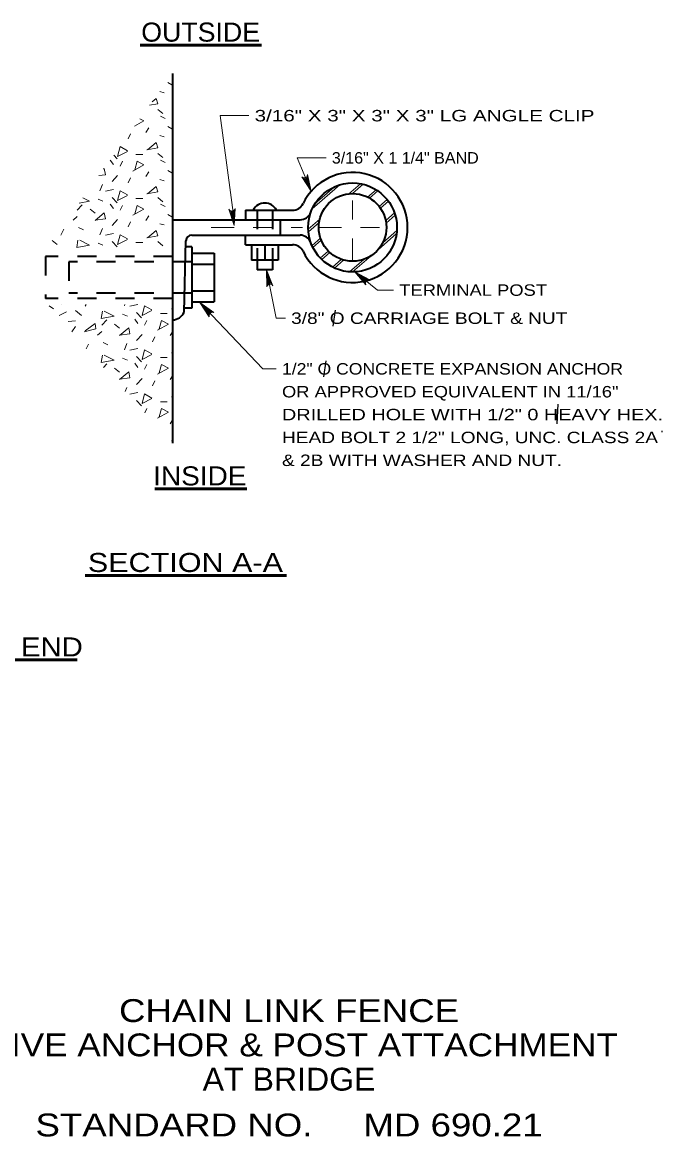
# Model space of a CAD drawing. Extents: x -29.89 to -22.78, y 99.65 to 109.34.
# Drawn here: x -26.25 to -22.88, y 99.65 to 105.5 of the extents above; entities that cross this region are included whole.
import ezdxf
from ezdxf.enums import TextEntityAlignment as Align

# ---------------------------------------------------------------- set-up
doc = ezdxf.new("R2010")
doc.units = 0
doc.header["$LTSCALE"] = 0.024
doc.linetypes.add('DOT_DASHED', pattern=[7.7, 5, -1.2, 0.3, -1.2])
doc.linetypes.add('SHORT_DASHED', pattern=[2.7, 1.5, -1.2])
for name, color, linetype, lineweight in [('1', 7, 'Continuous', 35), ('10', 7, 'Continuous', 13), ('12', 7, 'Continuous', 53), ('13', 7, 'Continuous', 25), ('6', 7, 'Continuous', 13)]:
    doc.layers.add(name, color=color, linetype=linetype, lineweight=lineweight)

msp = doc.modelspace()

# ---------------------------------------------------------------- linework, layer by layer
at = {"layer": '1'}
for p, q in [((-25.45667, 105.22985), (-25.45667, 103.29046)), ((-25.45667, 104.46217), (-24.78685, 104.46217)), ((-25.07283, 104.51269), (-24.82575, 104.51269)), ((-25.07283, 104.51269), (-25.07283, 104.46217)), ((-24.891, 104.46217), (-24.891, 104.38137)), ((-25.39606, 103.97733), (-25.38594, 104.35187)), ((-25.35565, 104.38137), (-24.78685, 104.38137)), ((-25.07283, 104.33085), (-25.07283, 104.38137)), ((-25.35565, 104.32075), (-25.38596, 104.32075)), ((-25.35565, 104.32075), (-25.35565, 103.99752)), ((-25.35469, 104.28652), (-25.23825, 104.28652)), ((-25.23825, 104.28652), (-25.23825, 104.03179)), ((-25.07283, 104.33085), (-24.82575, 104.33085)), ((-25.04252, 104.33085), (-25.04252, 104.25006)), ((-24.97181, 104.33085), (-24.97181, 104.25006)), ((-24.9011, 104.33085), (-24.9011, 104.25006)), ((-25.35469, 104.22829), (-25.23825, 104.22829)), ((-24.9011, 104.25006), (-25.04252, 104.25006)), ((-25.01223, 104.25006), (-25.01223, 104.19954)), ((-24.93142, 104.25006), (-24.93142, 104.19954)), ((-24.93142, 104.19954), (-25.01223, 104.19954)), ((-25.35469, 104.09), (-25.23825, 104.09)), ((-25.35565, 103.99752), (-25.39552, 103.99752)), ((-25.35469, 104.03179), (-25.23825, 104.03179))]:
    msp.add_line(p, q, dxfattribs=at)
at = {"layer": '1', "linetype": 'SHORT_DASHED'}
for p, q in [((-25.45667, 104.46217), (-25.35565, 104.46217)), ((-25.01223, 104.51269), (-25.01223, 104.25006)), ((-24.93142, 104.51269), (-24.93142, 104.25006)), ((-26.12333, 104.26925), (-26.12333, 104.04904)), ((-25.45667, 104.26925), (-26.12333, 104.26925)), ((-26.00212, 104.24096), (-26.00212, 104.07733)), ((-25.35565, 104.24096), (-26.00212, 104.24096)), ((-25.45667, 104.04904), (-26.12333, 104.04904)), ((-25.35565, 104.07733), (-26.00212, 104.07733))]:
    msp.add_line(p, q, dxfattribs=at)
at = {"layer": '1'}
for radius in [0.23333, 0.17778]:
    msp.add_circle((-24.51081, 104.42177), radius, dxfattribs=at)
for centre, radius, start, end in [((-24.51081, 104.42177), 0.28889, 205.69151, 154.30843), ((-24.97182, 104.48152), 0.06815, 27.21203, 152.78797), ((-24.82575, 104.57329), 0.06061, 270, 334.30843), ((-24.78684, 104.52278), 0.06061, 270, 339.901), ((-25.35564, 104.35106), 0.0303, 90, 178.45183), ((-24.78684, 104.32076), 0.06061, 20.09892, 90), ((-24.82575, 104.27025), 0.06061, 25.69151, 90), ((-25.45735, 104.0036), 0.06669, 270.58756, 336.79258)]:
    msp.add_arc(centre, radius, start, end, dxfattribs=at)
at = {"layer": '10', "linetype": 'DOT_DASHED'}
for p, q in [((-24.51081, 104.244), (-24.51081, 104.5945)), ((-25.2535, 104.42177), (-24.77335, 104.42177)), ((-24.68858, 104.42177), (-24.33302, 104.42177))]:
    msp.add_line(p, q, dxfattribs=at)
at = {"layer": '10'}
for p, q in [((-24.37971, 104.09292), (-24.4994, 104.18871)), ((-24.29552, 104.09292), (-24.37971, 104.09292))]:
    msp.add_line(p, q, dxfattribs=at)
at = {"layer": '10', "lineweight": 25}
for p, q in [((-24.61329, 103.90283), (-24.60112, 103.9881)), ((-24.66181, 103.63706), (-24.64965, 103.72235))]:
    msp.add_line(p, q, dxfattribs=at)
at = {"layer": '10'}
for points in [[(-25.05569, 105.0085), (-25.20694, 105.0085), (-25.13229, 104.46217)], [(-24.72802, 104.61225), (-24.80115, 104.78704), (-24.6499, 104.78704)], [(-24.72802, 104.61225), (-24.77733, 104.68727), (-24.77037, 104.68281), (-24.76356, 104.68187), (-24.75771, 104.68323), (-24.75265, 104.68644), (-24.74854, 104.69196), (-24.74681, 104.70006), (-24.72802, 104.61225), (-24.74854, 104.69196), (-24.75265, 104.68644), (-24.72802, 104.61225), (-24.75771, 104.68323), (-24.76356, 104.68187), (-24.72802, 104.61225), (-24.77037, 104.68281)], [(-25.13229, 104.43187), (-25.16065, 104.51708), (-25.15504, 104.51098), (-25.14871, 104.50831), (-25.14271, 104.5081), (-25.13698, 104.50992), (-25.13158, 104.51419), (-25.12783, 104.52156), (-25.13229, 104.43187), (-25.13158, 104.51419), (-25.13698, 104.50992), (-25.13229, 104.43187), (-25.14271, 104.5081), (-25.14871, 104.50831), (-25.13229, 104.43187), (-25.15504, 104.51098)], [(-24.86385, 103.94548), (-24.91181, 103.94548), (-24.96227, 104.19954)], [(-24.96227, 104.19954), (-24.92883, 104.11619), (-24.93479, 104.12196), (-24.94127, 104.12423), (-24.94727, 104.12408), (-24.95287, 104.12194), (-24.958, 104.11733), (-24.96131, 104.10975), (-24.96227, 104.19954), (-24.958, 104.11733), (-24.95287, 104.12194), (-24.96227, 104.19954), (-24.94727, 104.12408), (-24.94127, 104.12423), (-24.96227, 104.19954), (-24.93479, 104.12196)], [(-24.4994, 104.18871), (-24.42015, 104.14648), (-24.4284, 104.14704), (-24.43483, 104.14462), (-24.43933, 104.14062), (-24.44223, 104.13537), (-24.44319, 104.12856), (-24.44083, 104.12065), (-24.4994, 104.18871), (-24.44319, 104.12856), (-24.44223, 104.13537), (-24.4994, 104.18871), (-24.43933, 104.14062), (-24.43483, 104.14462), (-24.4994, 104.18871), (-24.4284, 104.14704)], [(-24.91181, 103.67971), (-24.9819, 103.67971), (-25.3166, 104.03179)], [(-25.31242, 104.02798), (-25.2396, 103.97542), (-25.24771, 103.97708), (-25.25442, 103.97556), (-25.2594, 103.97221), (-25.263, 103.9674), (-25.26487, 103.96077), (-25.2636, 103.9526), (-25.31242, 104.02798), (-25.26487, 103.96077), (-25.263, 103.9674), (-25.31242, 104.02798), (-25.2594, 103.97221), (-25.25442, 103.97556), (-25.31242, 104.02798), (-25.24771, 103.97708)]]:
    msp.add_lwpolyline(points, dxfattribs=at)
at = {"layer": '12'}
for p, q in [((-25.62696, 105.37844), (-24.98935, 105.37844)), ((-25.55012, 103.04929), (-25.06546, 103.04929)), ((-25.91608, 102.59488), (-24.85775, 102.59488)), ((-29.60256, 102.15167), (-25.95775, 102.15167))]:
    msp.add_line(p, q, dxfattribs=at)
at = {"layer": '13'}
msp.add_line((-23.4324, 103.49381), (-23.43829, 103.39044), dxfattribs=at)
at = {"layer": '6'}
for p, q in [((-25.48185, 105.18283), (-25.4594, 105.16998)), ((-25.52358, 105.13469), (-25.5011, 105.12827)), ((-25.53321, 105.04162), (-25.50752, 105.01917)), ((-25.52037, 105.00631), (-25.49469, 104.99348)), ((-25.5974, 104.91967), (-25.58133, 104.94535)), ((-25.48185, 104.95177), (-25.4594, 104.93894)), ((-25.67762, 104.91325), (-25.69046, 104.88758)), ((-25.52358, 104.90362), (-25.5011, 104.89721)), ((-25.53321, 104.81056), (-25.50752, 104.7881)), ((-25.78352, 104.77525), (-25.76748, 104.75279)), ((-25.76571, 104.80135), (-25.74821, 104.78169)), ((-25.71933, 104.76883), (-25.73217, 104.74317)), ((-25.64873, 104.80415), (-25.61344, 104.80415)), ((-25.52037, 104.77525), (-25.49469, 104.76242)), ((-25.745, 104.69502), (-25.7739, 104.66294)), ((-25.5974, 104.6886), (-25.58133, 104.71429)), ((-25.48185, 104.72071), (-25.4594, 104.70788)), ((-25.82523, 104.6469), (-25.83808, 104.61479)), ((-25.67762, 104.68219), (-25.69046, 104.65652)), ((-25.52358, 104.67256), (-25.5011, 104.66615)), ((-24.57829, 104.64512), (-24.72285, 104.51917)), ((-24.46958, 104.65144), (-24.53035, 104.59848)), ((-24.45596, 104.64856), (-24.51142, 104.60025)), ((-25.76748, 104.62123), (-25.80919, 104.61158)), ((-25.7739, 104.5795), (-25.74821, 104.55062)), ((-25.53321, 104.5795), (-25.50752, 104.55704)), ((-24.60819, 104.63381), (-24.70754, 104.54723)), ((-24.38746, 104.61983), (-24.43158, 104.5814)), ((-24.37781, 104.6135), (-24.42146, 104.57546)), ((-25.95681, 104.5121), (-25.93115, 104.541)), ((-25.88942, 104.51852), (-25.86375, 104.49606)), ((-25.84771, 104.56987), (-25.82202, 104.56025)), ((-25.78352, 104.54421), (-25.76748, 104.52173)), ((-25.71933, 104.53777), (-25.73217, 104.5121)), ((-25.64873, 104.57308), (-25.61344, 104.57308)), ((-25.52037, 104.54421), (-25.49469, 104.53135)), ((-24.32881, 104.56779), (-24.37073, 104.53125)), ((-24.32204, 104.55894), (-24.36415, 104.52225)), ((-25.97927, 104.46075), (-25.95681, 104.48002)), ((-25.745, 104.46398), (-25.7739, 104.43187)), ((-25.5974, 104.45754), (-25.58133, 104.48323)), ((-25.48185, 104.48965), (-25.4594, 104.47681)), ((-24.68317, 104.46529), (-24.74396, 104.41233)), ((-24.29033, 104.49815), (-24.33671, 104.45773)), ((-24.28667, 104.4866), (-24.33454, 104.44487)), ((-26.04346, 104.38054), (-26.02742, 104.41262)), ((-25.9504, 104.42225), (-25.92473, 104.40942)), ((-25.82523, 104.41583), (-25.83808, 104.38375)), ((-25.67762, 104.45112), (-25.69046, 104.42546)), ((-25.52358, 104.4415), (-25.5011, 104.43508)), ((-24.68671, 104.44748), (-24.74298, 104.39846)), ((-24.27802, 104.40571), (-24.35256, 104.34073)), ((-26.08885, 104.35329), (-26.06271, 104.3324)), ((-25.76748, 104.39017), (-25.80919, 104.38054)), ((-25.7739, 104.34844), (-25.74821, 104.31956)), ((-25.64873, 104.34202), (-25.61344, 104.34202)), ((-25.53321, 104.34844), (-25.50752, 104.32598)), ((-24.67902, 104.36575), (-24.72387, 104.32667)), ((-24.67527, 104.35427), (-24.71892, 104.31625)), ((-24.27971, 104.38948), (-24.37704, 104.30467)), ((-25.84771, 104.33881), (-25.82202, 104.32919)), ((-24.6384, 104.29798), (-24.68033, 104.26144)), ((-24.6304, 104.29023), (-24.6725, 104.25354)), ((-24.57023, 104.25423), (-24.6166, 104.21381)), ((-24.55779, 104.25031), (-24.60567, 104.2086)), ((-24.45217, 104.25394), (-24.52671, 104.18898)), ((-24.4131, 104.27325), (-24.51042, 104.18844)), ((-26.10421, 104.01127), (-26.08175, 103.99523)), ((-26.03998, 104.01773), (-26.04002, 104.01769)), ((-25.91487, 104.00806), (-25.91004, 104.01773)), ((-25.7069, 104.01773), (-25.70948, 104.01127)), ((-25.63887, 104.01769), (-25.6806, 104.00806)), ((-25.46237, 103.99523), (-25.45667, 103.99617)), ((-25.45667, 103.99735), (-25.45917, 103.99523)), ((-26.01435, 103.97917), (-26.05285, 103.95992)), ((-25.96621, 103.98558), (-25.93412, 103.95992)), ((-25.82823, 103.90856), (-25.80254, 103.93746)), ((-25.7191, 103.96633), (-25.69344, 103.95671)), ((-25.65492, 103.94067), (-25.63887, 103.91821)), ((-25.64529, 103.97596), (-25.61962, 103.94708)), ((-25.59075, 103.93425), (-25.60358, 103.90856)), ((-25.52015, 103.96954), (-25.48483, 103.96954)), ((-26.00473, 103.92783), (-25.96621, 103.93104)), ((-25.98548, 103.87327), (-25.96621, 103.90215)), ((-25.85069, 103.85723), (-25.82823, 103.87648)), ((-25.76083, 103.915), (-25.73515, 103.89252)), ((-25.82181, 103.81871), (-25.79612, 103.80588)), ((-25.61642, 103.86044), (-25.64529, 103.82833)), ((-25.54902, 103.8476), (-25.56185, 103.82192)), ((-25.46879, 103.85402), (-25.45667, 103.87342)), ((-25.91056, 103.7856), (-25.89881, 103.80908)), ((-25.69665, 103.81229), (-25.70948, 103.78021)), ((-25.63887, 103.78663), (-25.6806, 103.777)), ((-25.46237, 103.76417), (-25.45667, 103.7651)), ((-25.45667, 103.76631), (-25.45917, 103.76417)), ((-25.81998, 103.68679), (-25.80254, 103.7064)), ((-25.7191, 103.73527), (-25.69344, 103.72565)), ((-25.65492, 103.7096), (-25.63887, 103.68715)), ((-25.64529, 103.7449), (-25.61962, 103.71602)), ((-25.59075, 103.70319), (-25.60358, 103.67752)), ((-25.52015, 103.73848), (-25.48483, 103.73848)), ((-25.76083, 103.68394), (-25.73515, 103.66146)), ((-25.46879, 103.62296), (-25.45667, 103.64235)), ((-25.69665, 103.58123), (-25.70471, 103.56106)), ((-25.61642, 103.62937), (-25.64529, 103.59729)), ((-25.54902, 103.61654), (-25.56185, 103.59085)), ((-25.63887, 103.55556), (-25.6806, 103.54594)), ((-25.46237, 103.5331), (-25.45667, 103.53404)), ((-25.45667, 103.53525), (-25.45917, 103.5331)), ((-25.64529, 103.51383), (-25.61962, 103.48496)), ((-25.59075, 103.47212), (-25.60219, 103.44921)), ((-25.52015, 103.50742), (-25.48483, 103.50742)), ((-25.46879, 103.3919), (-25.45667, 103.41129)), ((-25.46237, 103.30204), (-25.45667, 103.30298)), ((-25.45667, 103.30419), (-25.45917, 103.30204))]:
    msp.add_line(p, q, dxfattribs=at)
for points in [[(-25.57683, 105.06323), (-25.53321, 105.0705), (-25.54283, 105.0994), (-25.56358, 105.08158)], [(-25.65604, 104.95342), (-25.60702, 104.98065), (-25.6281, 104.99215)], [(-25.59096, 104.82981), (-25.53321, 104.83944), (-25.54283, 104.86833), (-25.58775, 104.82981)], [(-25.69367, 104.82019), (-25.745, 104.79452), (-25.73217, 104.84585), (-25.69367, 104.8234)], [(-25.66477, 104.7175), (-25.60702, 104.74958), (-25.64231, 104.76883), (-25.65515, 104.72392)], [(-25.84294, 104.69427), (-25.80919, 104.69825), (-25.8156, 104.73033), (-25.81912, 104.72729)], [(-25.59096, 104.59875), (-25.53321, 104.60837), (-25.54283, 104.63727), (-25.58775, 104.59875)], [(-25.94706, 104.54988), (-25.89262, 104.56025), (-25.92715, 104.5775)], [(-25.69367, 104.58912), (-25.745, 104.56346), (-25.73217, 104.61479), (-25.69367, 104.59233)], [(-25.66477, 104.48644), (-25.60702, 104.51852), (-25.64231, 104.53777), (-25.65515, 104.49285)], [(-25.86375, 104.46075), (-25.80919, 104.46719), (-25.8156, 104.49927), (-25.86375, 104.45754)], [(-25.59096, 104.36769), (-25.53321, 104.37731), (-25.54283, 104.40621), (-25.58775, 104.36769)], [(-25.9536, 104.35485), (-25.96002, 104.31635), (-25.89262, 104.32919), (-25.94398, 104.35485)], [(-25.69367, 104.35806), (-25.745, 104.3324), (-25.73217, 104.38375), (-25.69367, 104.36127)], [(-25.56506, 103.98558), (-25.61642, 103.95992), (-25.60358, 104.01127), (-25.56506, 103.98879)], [(-25.82502, 103.98237), (-25.83144, 103.94387), (-25.76404, 103.95671), (-25.81537, 103.98237)], [(-25.53619, 103.8829), (-25.47842, 103.915), (-25.51373, 103.93425), (-25.52656, 103.88931)], [(-25.92129, 103.87327), (-25.86031, 103.88931), (-25.86352, 103.91821), (-25.91487, 103.87969)], [(-25.73515, 103.85723), (-25.6806, 103.86365), (-25.68702, 103.89573), (-25.73515, 103.85402)], [(-25.56506, 103.75454), (-25.61642, 103.72885), (-25.60358, 103.78021), (-25.56506, 103.75775)], [(-25.82502, 103.75131), (-25.83144, 103.71281), (-25.76404, 103.72565), (-25.81537, 103.75131)], [(-25.53619, 103.65183), (-25.47842, 103.68394), (-25.51373, 103.70319), (-25.52656, 103.65825)], [(-25.73515, 103.62617), (-25.6806, 103.63258), (-25.68702, 103.66467), (-25.73515, 103.62296)], [(-25.56506, 103.52348), (-25.61642, 103.49779), (-25.60358, 103.54915), (-25.56506, 103.52669)], [(-25.53619, 103.42077), (-25.47842, 103.45287), (-25.51373, 103.47212), (-25.52656, 103.42719)]]:
    msp.add_lwpolyline(points, dxfattribs=at)

# ---------------------------------------------------------------- texts
at = {"layer": '12'}
for s, width, p in [('OUTSIDE', 1.05, (-25.30882, 105.39702)), ('INSIDE', 1.1, (-25.31328, 103.0679)), ('SECTION A-A', 1.2, (-25.38895, 102.61347)), ('ALTERNATE POST ATTACHMENT AT BRIDGE END', 1.15, (-27.77772, 102.17026))]:
    msp.add_text(s, height=0.1, dxfattribs=dict(at, width=width)).set_placement(p, align=Align.CENTER)
for s, width, p in [('3/16" X 3" X 3" X 3" LG ANGLE CLIP', 1.35, (-25.02538, 104.9785)), ('3/16" X 1 1/4" BAND', 1.05, (-24.61958, 104.75703)), ('TERMINAL POST', 1.2, (-24.26521, 104.06292)), ('3/8" O CARRIAGE BOLT & NUT', 1.25, (-24.83354, 103.91547)), ('1/2" O CONCRETE EXPANSION ANCHOR', 1.15, (-24.8815, 103.64971)), ('OR APPROVED EQUIVALENT IN 11/16"', 1.2, (-24.8815, 103.52971)), ('DRILLED HOLE WITH 1/2" 0 HEAVY HEX.', 1.3, (-24.8815, 103.40971)), ('HEAD BOLT 2 1/2" LONG, UNC. CLASS 2A', 1.25, (-24.8815, 103.28971)), ('& 2B WITH WASHER AND NUT.', 1.25, (-24.8815, 103.16971))]:
    msp.add_text(s, height=0.06, dxfattribs=dict(at, width=width)).set_placement(p)
at = {"layer": '13'}
msp.add_text('.', height=0.06061, dxfattribs=at).set_placement((-22.88519, 103.3461), align=Align.CENTER)
for s, width, p in [('CHAIN LINK FENCE', 1.2, (-24.84433, 100.25164)), ('DRIVE ANCHOR & POST ATTACHMENT', 1.15, (-24.84433, 100.07164)), ('AT BRIDGE', 1.05, (-24.84433, 99.89164)), ('STANDARD NO.     MD 690.21', 1.2, (-24.84433, 99.65148))]:
    msp.add_text(s, height=0.12, dxfattribs=dict(at, width=width)).set_placement(p, align=Align.CENTER)

doc.saveas('drawing.dxf')
